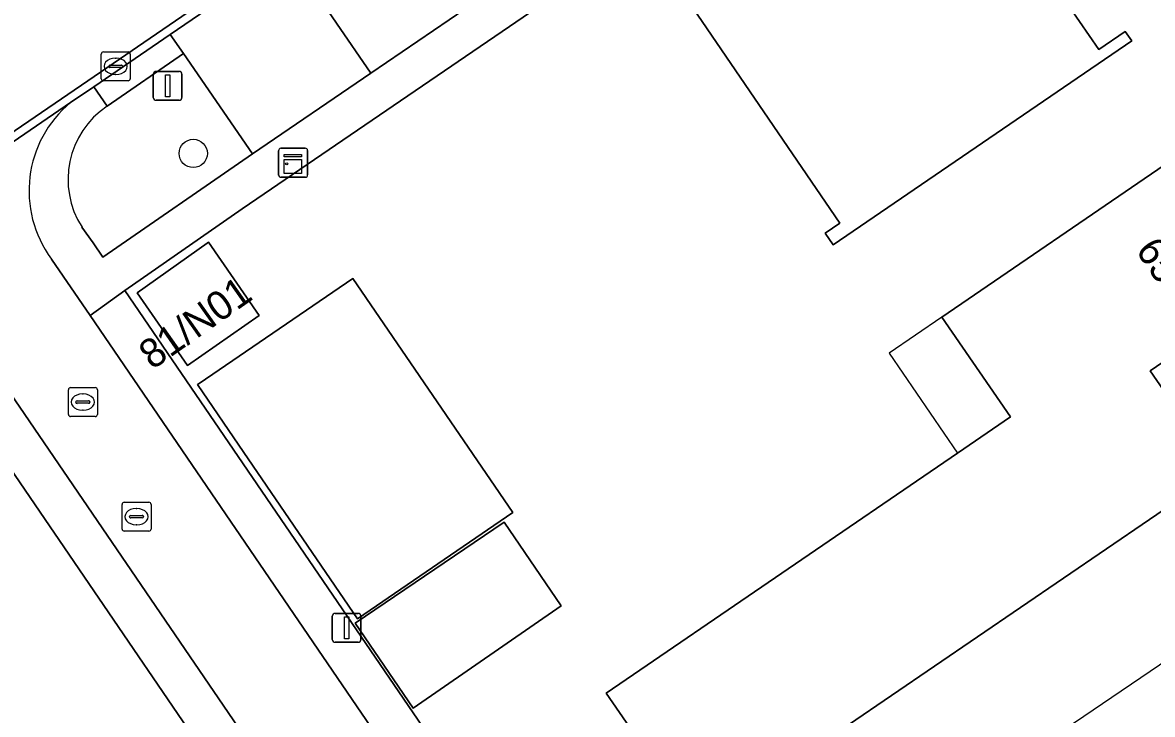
# Model space of a CAD drawing. Extents: x 155275 to 156265, y 382654 to 383635.
# Drawn here: x 155451.03 to 155490.05, y 383279.12 to 383303.02 of the extents above; entities that cross this region are included whole.
import ezdxf

# ---------------------------------------------------------------- set-up
doc = ezdxf.new("R2010")
doc.units = 0
for name, color, linetype in [('IMGEO_Boom', 7, 'Continuous'), ('IMGEO_Erf', 7, 'Continuous'), ('IMGEO_Groenvoorziening', 7, 'Continuous'), ('IMGEO_Kast', 7, 'Continuous'), ('IMGEO_Kolk', 7, 'Continuous'), ('IMGEO_Lichtmast', 7, 'Continuous'), ('IMGEO_Pand', 7, 'Continuous'), ('IMGEO_Pand_nummerreeks', 7, 'Continuous'), ('IMGEO_Pand_overbouw', 7, 'Continuous'), ('IMGEO_Parkeervlak_open', 7, 'Continuous'), ('IMGEO_Rijbaan_lokaal_open', 7, 'Continuous'), ('IMGEO_Rioolput', 7, 'Continuous'), ('IMGEO_Voetpad_open', 7, 'Continuous')]:
    doc.layers.add(name, color=color, linetype=linetype)

msp = doc.modelspace()

# ---------------------------------------------------------------- linework, layer by layer
at = {"layer": 'IMGEO_Boom'}
msp.add_circle((155456.922, 383298.499), 0.489, dxfattribs=at)
at = {"layer": 'IMGEO_Erf'}
for points in [[(155498.922, 383291.025), (155490.365, 383303.561), (155484.692, 383311.871), (155483.519, 383313.595), (155458.608, 383296.58), (155454.563, 383293.76), (155518.365, 383200.253), (155523.731, 383203.931), (155542.221, 383216.713), (155538.669, 383221.857), (155525.357, 383212.738), (155524.015, 383214.705), (155523.982, 383214.682), (155523.259, 383215.732), (155518.011, 383212.12), (155515.657, 383215.542), (155521.261, 383219.398), (155522.097, 383218.189), (155539.024, 383229.787), (155546.127, 383219.41), (155547.42, 383220.262)], [(155479.026, 383295.337), (155478.746, 383295.745), (155479.257, 383296.096), (155472.866, 383305.465), (155472.33, 383305.097), (155472.047, 383305.51), (155478.777, 383310.12), (155478.999, 383309.792), (155478.75, 383309.624), (155479.613, 383308.378), (155482.489, 383310.333), (155485.946, 383305.261), (155485.996, 383305.295), (155486.531, 383304.516), (155488.193, 383302.091), (155489.109, 383302.716), (155489.333, 383302.394)], [(155478.068, 383277.739), (155478.914, 383276.501), (155475.766, 383274.346), (155477.88, 383271.261), (155472.514, 383267.589), (155470.402, 383270.675), (155467.861, 383274.42), (155472.672, 383277.696), (155471.178, 383279.852), (155483.314, 383288.146), (155485.141, 383289.394), (155482.779, 383292.843), (155490.457, 383298.092), (155493.615, 383293.483), (155489.973, 383290.987), (155491.346, 383288.985), (155490.44, 383288.371), (155490.41, 383288.351), (155491.433, 383286.863)], [(155459.2, 383292.899), (155456.718, 383291.167), (155454.983, 383293.686), (155457.403, 383295.404), (155457.451, 383295.438)], [(155467.96, 383286.091), (155462.597, 383282.421), (155458.672, 383288.17), (155457.073, 383290.512), (155457.123, 383290.546), (155462.435, 383294.173)], [(155469.63, 383282.862), (155464.518, 383279.333), (155462.516, 383282.274), (155467.661, 383285.757)]]:
    msp.add_lwpolyline(points, close=True, dxfattribs=at)
msp.add_lwpolyline([(155428.923, 383238.236), (155433.772, 383231.088), (155444.08, 383215.943), (155444.194, 383215.772), (155445.521, 383213.792), (155474.854, 383170.583), (155512.727, 383196.487), (155448.882, 383290.128), (155420.301, 383270.554)], dxfattribs=at)
at = {"layer": 'IMGEO_Groenvoorziening'}
msp.add_lwpolyline([(155465.016, 383307.71), (155460.68, 383304.739), (155463.05, 383301.268), (155467.389, 383304.232)], close=True, dxfattribs=at)
for points in [[(155453.08, 383295.953), (155453.466, 383295.407), (155453.795, 383294.911), (155458.97, 383298.483), (155456.58, 383301.953)], [(155456.58, 383301.953), (155453.951, 383300.137)]]:
    msp.add_lwpolyline(points, dxfattribs=at)
msp.add_arc((155455.648, 383297.601), 3.051, 123.7852, 212.6957, dxfattribs=at)
at = {"layer": 'IMGEO_Kast'}
for p, q in [((155459.871, 383297.752), (155459.871, 383298.593)), ((155459.871, 383298.593), (155459.871, 383297.752)), ((155459.946, 383298.677), (155460.787, 383298.677)), ((155460.787, 383298.677), (155459.946, 383298.677)), ((155460.871, 383298.602), (155460.871, 383297.761)), ((155460.871, 383297.761), (155460.871, 383298.602)), ((155460.796, 383297.677), (155459.955, 383297.677)), ((155459.955, 383297.677), (155460.796, 383297.677))]:
    msp.add_line(p, q, dxfattribs=at)
for points in [[(155460.066, 383298.467), (155460.666, 383298.467), (155460.666, 383298.382), (155460.066, 383298.382), (155460.066, 383298.467)], [(155460.066, 383298.292), (155460.666, 383298.292), (155460.666, 383297.803), (155460.066, 383297.803), (155460.066, 383298.292)]]:
    msp.add_lwpolyline(points, dxfattribs=at)
msp.add_circle((155460.15, 383298.141), 0.0377, dxfattribs=at)
for centre, start, end in [((155459.949, 383298.599), 92.4484, 184.2845), ((155459.949, 383298.599), 92.4484, 184.2845), ((155460.793, 383298.599), 2.4484, 94.2845), ((155460.793, 383298.599), 2.4484, 94.2845), ((155459.949, 383297.755), 182.4484, 274.2845), ((155459.949, 383297.755), 182.4484, 274.2845), ((155460.793, 383297.755), 272.4484, 4.2845), ((155460.793, 383297.755), 272.4484, 4.2845)]:
    msp.add_arc(centre, 0.0779, start, end, dxfattribs=at)
at = {"layer": 'IMGEO_Kolk'}
for p, q in [((155453.818, 383302.009), (155454.67, 383302.009)), ((155453.743, 383301.083), (155453.743, 383301.935)), ((155454.231, 383301.789), (155454.256, 383301.789)), ((155454.744, 383301.935), (155454.744, 383301.083)), ((155454.002, 383301.503), (155454.002, 383301.515)), ((155454.44, 383301.466), (155454.042, 383301.466)), ((155454.045, 383301.552), (155454.443, 383301.552)), ((155454.254, 383301.229), (155454.229, 383301.229)), ((155454.486, 383301.515), (155454.486, 383301.503)), ((155454.67, 383301.009), (155453.818, 383301.009)), ((155452.61, 383289.482), (155452.61, 383290.334)), ((155452.685, 383290.408), (155453.537, 383290.408)), ((155453.611, 383290.334), (155453.611, 383289.482)), ((155452.869, 383289.902), (155452.869, 383289.914)), ((155453.307, 383289.865), (155452.909, 383289.865)), ((155452.912, 383289.951), (155453.31, 383289.951)), ((155453.098, 383290.188), (155453.123, 383290.188)), ((155453.353, 383289.914), (155453.353, 383289.902)), ((155453.121, 383289.628), (155453.096, 383289.628)), ((155453.537, 383289.408), (155452.685, 383289.408))]:
    msp.add_line(p, q, dxfattribs=at)
for points in [[(155453.818, 383302.009), (155454.67, 383302.009)], [(155453.743, 383301.083), (155453.743, 383301.935)], [(155454.744, 383301.935), (155454.744, 383301.083)], [(155454.67, 383301.009), (155453.818, 383301.009)], [(155452.61, 383289.482), (155452.61, 383290.334)], [(155452.685, 383290.408), (155453.537, 383290.408)], [(155453.611, 383290.334), (155453.611, 383289.482)], [(155453.537, 383289.408), (155452.685, 383289.408)]]:
    msp.add_lwpolyline(points, dxfattribs=at)
for centre, radius, start, end in [((155453.82, 383301.933), 0.0765, 91.552, 178.448), ((155453.82, 383301.933), 0.0765, 91.552, 178.448), ((155454.668, 383301.933), 0.0765, 1.552, 88.448), ((155454.668, 383301.933), 0.0765, 1.552, 88.448), ((155454.042, 383301.512), 0.0403, 85.8775, 175.7526), ((155454.039, 383301.502), 0.0366, 178.938, 274.7102), ((155454.443, 383301.509), 0.043, 264.8664, 352.4533), ((155454.447, 383301.514), 0.0386, 1.7309, 96.639), ((155453.82, 383301.085), 0.0765, 181.552, 268.448), ((155453.82, 383301.085), 0.0765, 181.552, 268.448), ((155454.668, 383301.085), 0.0765, 271.552, 358.448), ((155454.668, 383301.085), 0.0765, 271.552, 358.448), ((155452.687, 383290.332), 0.0765, 91.552, 178.448), ((155452.687, 383290.332), 0.0765, 91.552, 178.448), ((155453.535, 383290.332), 0.0765, 1.552, 88.448), ((155453.535, 383290.332), 0.0765, 1.552, 88.448), ((155452.909, 383289.911), 0.0403, 85.8775, 175.7526), ((155452.906, 383289.901), 0.0366, 178.938, 274.7102), ((155453.31, 383289.908), 0.043, 264.8664, 352.4533), ((155453.314, 383289.913), 0.0386, 1.7309, 96.639), ((155452.687, 383289.484), 0.0765, 181.552, 268.448), ((155452.687, 383289.484), 0.0765, 181.552, 268.448), ((155453.535, 383289.484), 0.0765, 271.552, 358.448), ((155453.535, 383289.484), 0.0765, 271.552, 358.448)]:
    msp.add_arc(centre, radius, start, end, dxfattribs=at)
for centre, major_axis, ratio, start_param, end_param in [((155454.23, 383301.509), (-0.387, 0.002), 0.722429, 4.712389, 7.853982), ((155454.255, 383301.509), (-0.39, 0.002), 0.717154, 1.570796, 4.712389), ((155453.097, 383289.908), (-0.387, 0.002), 0.722429, 4.712389, 7.853982), ((155453.122, 383289.908), (-0.39, 0.002), 0.717154, 1.570796, 4.712389)]:
    msp.add_ellipse(centre, major_axis=major_axis, ratio=ratio, start_param=start_param, end_param=end_param, dxfattribs=at)
at = {"layer": 'IMGEO_Lichtmast'}
for p, q in [((155455.543, 383300.436), (155455.543, 383301.236)), ((155455.543, 383301.236), (155455.543, 383300.436)), ((155455.643, 383301.336), (155456.433, 383301.336)), ((155456.433, 383301.336), (155455.643, 383301.336)), ((155456.533, 383301.236), (155456.533, 383300.436)), ((155456.533, 383300.436), (155456.533, 383301.236)), ((155456.433, 383300.336), (155455.643, 383300.336)), ((155455.643, 383300.336), (155456.433, 383300.336)), ((155461.725, 383281.707), (155461.725, 383282.507)), ((155461.725, 383282.507), (155461.725, 383281.707)), ((155461.825, 383282.607), (155462.615, 383282.607)), ((155462.615, 383282.607), (155461.825, 383282.607)), ((155462.715, 383282.507), (155462.715, 383281.707)), ((155462.715, 383281.707), (155462.715, 383282.507)), ((155462.615, 383281.607), (155461.825, 383281.607)), ((155461.825, 383281.607), (155462.615, 383281.607))]:
    msp.add_line(p, q, dxfattribs=at)
for points in [[(155455.963, 383301.211), (155456.113, 383301.211), (155456.113, 383300.461), (155455.963, 383300.461), (155455.963, 383301.211)], [(155462.145, 383282.482), (155462.295, 383282.482), (155462.295, 383281.732), (155462.145, 383281.732), (155462.145, 383282.482)]]:
    msp.add_lwpolyline(points, dxfattribs=at)
for centre, start, end in [((155455.643, 383301.236), 90, 180), ((155455.643, 383301.236), 90, 180), ((155456.433, 383301.236), 0, 90), ((155456.433, 383301.236), 360, 90), ((155455.643, 383300.436), 180, 270), ((155455.643, 383300.436), 180, 270), ((155456.433, 383300.436), 270, 0), ((155456.433, 383300.436), 270, 0), ((155461.825, 383282.507), 90, 180), ((155461.825, 383282.507), 90, 180), ((155462.615, 383282.507), 0, 90), ((155462.615, 383282.507), 360, 90), ((155461.825, 383281.707), 180, 270), ((155461.825, 383281.707), 180, 270), ((155462.615, 383281.707), 270, 0), ((155462.615, 383281.707), 270, 0)]:
    msp.add_arc(centre, 0.1, start, end, dxfattribs=at)
at = {"layer": 'IMGEO_Pand'}
for points in [[(155485.946, 383305.261), (155482.489, 383310.333), (155479.613, 383308.378), (155478.75, 383309.624), (155478.999, 383309.792), (155478.777, 383310.12), (155472.047, 383305.51), (155472.33, 383305.097), (155472.866, 383305.465), (155479.257, 383296.096), (155478.746, 383295.745), (155479.026, 383295.337), (155489.333, 383302.394), (155489.109, 383302.716), (155488.193, 383302.091), (155486.531, 383304.516), (155485.996, 383305.295)], [(155491.433, 383286.863), (155490.41, 383288.351), (155490.44, 383288.371), (155491.346, 383288.985), (155489.973, 383290.987), (155493.615, 383293.483), (155490.457, 383298.092), (155482.779, 383292.843), (155485.141, 383289.394), (155483.314, 383288.146), (155471.178, 383279.852), (155472.672, 383277.696), (155467.861, 383274.42), (155470.402, 383270.675), (155475.766, 383274.346), (155478.914, 383276.501), (155478.068, 383277.739)], [(155457.451, 383295.438), (155457.403, 383295.404), (155454.983, 383293.686), (155456.718, 383291.167), (155459.2, 383292.899)], [(155462.435, 383294.173), (155457.123, 383290.546), (155457.073, 383290.512), (155458.672, 383288.17), (155462.597, 383282.421), (155467.96, 383286.091)], [(155469.63, 383282.862), (155467.661, 383285.757), (155462.516, 383282.274), (155464.518, 383279.333)]]:
    msp.add_lwpolyline(points, close=True, dxfattribs=at)
at = {"layer": 'IMGEO_Pand_overbouw'}
for points in [[(155480.953, 383291.595), (155483.314, 383288.146), (155485.141, 383289.394), (155482.779, 383292.843)], [(155491.29, 383281.5), (155485.354, 383277.463), (155490.963, 383269.23), (155496.909, 383273.269)]]:
    msp.add_lwpolyline(points, close=True, dxfattribs=at)
at = {"layer": 'IMGEO_Parkeervlak_open'}
msp.add_lwpolyline([(155460.68, 383304.739), (155460.21, 383305.41), (155456.125, 383302.612), (155456.58, 383301.953), (155458.97, 383298.483), (155463.05, 383301.268)], close=True, dxfattribs=at)
at = {"layer": 'IMGEO_Rijbaan_lokaal_open'}
for points in [[(155549.095, 383366.65), (155548.143, 383365.998), (155500.38, 383333.268), (155453.502, 383301.158), (155415.989, 383275.504), (155413.779, 383278.713), (155450.858, 383304.106), (155512.791, 383346.508), (155545.973, 383369.225), (155600.872, 383406.808)], [(155424.682, 383281.084), (155430.818, 383285.286), (155434.134, 383287.556), (155438.198, 383290.339), (155443.006, 383293.63), (155443.354, 383293.869), (155452.688, 383300.259), (155453.487, 383300.806), (155456.125, 383302.612), (155460.21, 383305.41), (155464.555, 383308.385), (155468.641, 383311.184), (155473.267, 383314.353), (155477.352, 383317.15), (155479.909, 383318.901), (155481.111, 383319.724), (155489.301, 383325.333), (155490.548, 383326.188)], [(155452.688, 383300.259), (155443.354, 383293.869)], [(155453.361, 383292.898), (155452.03, 383294.85)], [(155448.903, 383292.685), (155450.079, 383290.961), (155513.95, 383197.324), (155515.231, 383195.446)], [(155518.343, 383197.603), (155517.119, 383199.399), (155453.361, 383292.898)]]:
    msp.add_lwpolyline(points, dxfattribs=at)
msp.add_lwpolyline([(155548.143, 383365.998), (155545.973, 383369.225), (155512.791, 383346.508), (155450.858, 383304.106), (155413.779, 383278.713), (155415.989, 383275.504), (155453.502, 383301.158), (155500.38, 383333.268)], close=True, dxfattribs=at)
msp.add_arc((155455.209, 383297.208), 3.958, 129.5687, 216.5595, dxfattribs=at)
at = {"layer": 'IMGEO_Rioolput'}
for p, q in [((155454.464, 383285.522), (155454.464, 383286.374)), ((155454.539, 383286.448), (155455.391, 383286.448)), ((155455.465, 383286.374), (155455.465, 383285.522)), ((155454.723, 383285.942), (155454.723, 383285.954)), ((155454.766, 383285.991), (155455.164, 383285.991)), ((155454.952, 383286.228), (155454.977, 383286.228)), ((155455.207, 383285.954), (155455.207, 383285.942)), ((155455.161, 383285.905), (155454.763, 383285.905)), ((155454.975, 383285.668), (155454.95, 383285.668)), ((155455.391, 383285.448), (155454.539, 383285.448))]:
    msp.add_line(p, q, dxfattribs=at)
for points in [[(155454.464, 383285.522), (155454.464, 383286.374)], [(155454.539, 383286.448), (155455.391, 383286.448)], [(155455.465, 383286.374), (155455.465, 383285.522)], [(155455.391, 383285.448), (155454.539, 383285.448)]]:
    msp.add_lwpolyline(points, dxfattribs=at)
for centre, radius, start, end in [((155454.541, 383286.372), 0.0765, 91.552, 178.448), ((155454.541, 383286.372), 0.0765, 91.552, 178.448), ((155455.389, 383286.372), 0.0765, 1.552, 88.448), ((155455.389, 383286.372), 0.0765, 1.552, 88.448), ((155454.763, 383285.951), 0.0403, 85.8775, 175.7526), ((155455.168, 383285.953), 0.0386, 1.7309, 96.639), ((155454.76, 383285.941), 0.0366, 178.938, 274.7102), ((155455.164, 383285.948), 0.043, 264.8664, 352.4533), ((155454.541, 383285.524), 0.0765, 181.552, 268.448), ((155454.541, 383285.524), 0.0765, 181.552, 268.448), ((155455.389, 383285.524), 0.0765, 271.552, 358.448), ((155455.389, 383285.524), 0.0765, 271.552, 358.448)]:
    msp.add_arc(centre, radius, start, end, dxfattribs=at)
for centre, major_axis, ratio, start_param, end_param in [((155454.951, 383285.948), (-0.387, 0.002), 0.722429, 4.712389, 7.853982), ((155454.976, 383285.948), (-0.39, 0.002), 0.717154, 1.570796, 4.712389)]:
    msp.add_ellipse(centre, major_axis=major_axis, ratio=ratio, start_param=start_param, end_param=end_param, dxfattribs=at)
at = {"layer": 'IMGEO_Voetpad_open'}
for points in [[(155458.608, 383296.58), (155483.519, 383313.595), (155482.752, 383314.722), (155480.188, 383312.991), (155476.098, 383310.206), (155471.484, 383307.029), (155467.389, 383304.232), (155463.05, 383301.268), (155458.97, 383298.483), (155453.795, 383294.911), (155453.466, 383295.407), (155453.08, 383295.953)], [(155453.951, 383300.137), (155453.487, 383300.806), (155452.688, 383300.259)], [(155452.03, 383294.85), (155453.361, 383292.898), (155454.563, 383293.76), (155458.608, 383296.58)]]:
    msp.add_lwpolyline(points, dxfattribs=at)
for points in [[(155456.58, 383301.953), (155456.125, 383302.612), (155453.487, 383300.806), (155453.951, 383300.137)], [(155454.563, 383293.76), (155453.361, 383292.898), (155517.119, 383199.399), (155518.365, 383200.253)], [(155450.079, 383290.961), (155448.882, 383290.128), (155512.727, 383196.487), (155513.95, 383197.324)]]:
    msp.add_lwpolyline(points, close=True, dxfattribs=at)
for centre, radius, start, end in [((155455.209, 383297.208), 3.958, 129.5687, 216.5595), ((155455.648, 383297.601), 3.051, 123.7852, 212.6957)]:
    msp.add_arc(centre, radius, start, end, dxfattribs=at)

# ---------------------------------------------------------------- texts
at = {"layer": 'IMGEO_Pand_nummerreeks'}
for s, rotation, p in [('65', 304.4174, (155489.441, 383295.153)), ('81/N01', 35.1681, (155455.508, 383291.005))]:
    msp.add_text(s, height=1, rotation=rotation, dxfattribs=at).set_placement(p)

doc.saveas('drawing.dxf')
